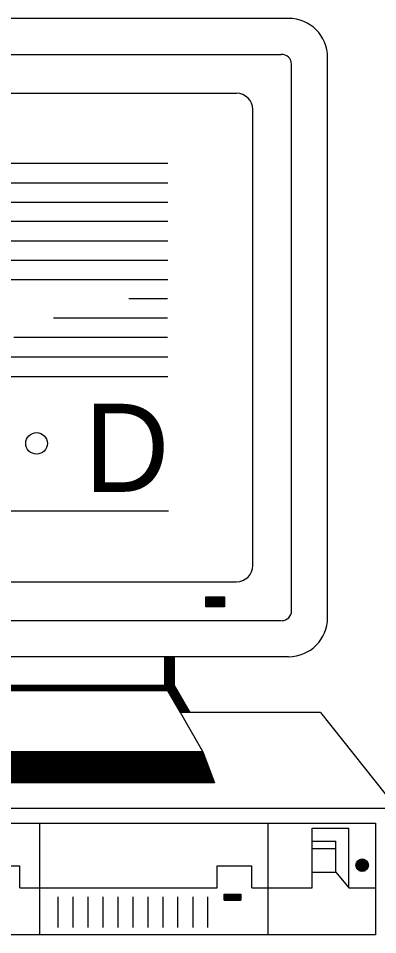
# Model space of a CAD drawing. Extents: x 22369.62 to 22373.29, y 22369.62 to 22372.46.
# Drawn here: x 22372.9001 to 22372.9507, y 22369.7343 to 22369.8633 of the extents above; entities that cross this region are included whole.
import ezdxf

# ---------------------------------------------------------------- set-up
doc = ezdxf.new("R2010")
doc.units = 0
for name, color, linetype in [('Level 2', 7, 'Continuous'), ('Level 25', 7, 'Continuous'), ('Level 3', 7, 'Continuous'), ('Level 5', 7, 'Continuous'), ('Level 7', 7, 'Continuous')]:
    doc.layers.add(name, color=color, linetype=linetype)

msp = doc.modelspace()

# ---------------------------------------------------------------- linework, layer by layer
at = {"layer": 'Level 2'}
for p, q in [((22372.85196, 22369.85273), (22372.93081, 22369.85273)), ((22372.9331, 22369.78628), (22372.9331, 22369.85044)), ((22372.85196, 22369.78399), (22372.93081, 22369.78399)), ((22372.92649, 22369.78183), (22372.9291, 22369.78183)), ((22372.92649, 22369.78176), (22372.9291, 22369.78176)), ((22372.92649, 22369.78168), (22372.9291, 22369.78168)), ((22372.92649, 22369.78158), (22372.9291, 22369.78158)), ((22372.92649, 22369.7815), (22372.9291, 22369.7815)), ((22372.92649, 22369.78143), (22372.9291, 22369.78143)), ((22372.92649, 22369.78134), (22372.9291, 22369.78134)), ((22372.92649, 22369.78126), (22372.9291, 22369.78126)), ((22372.92649, 22369.78118), (22372.9291, 22369.78118)), ((22372.92649, 22369.78109), (22372.9291, 22369.78109)), ((22372.92649, 22369.78101), (22372.9291, 22369.78101)), ((22372.92649, 22369.78093), (22372.9291, 22369.78093)), ((22372.92649, 22369.78085), (22372.9291, 22369.78085)), ((22372.92649, 22369.78076), (22372.9291, 22369.78076)), ((22372.92649, 22369.78068), (22372.9291, 22369.78068)), ((22372.92649, 22369.7806), (22372.9291, 22369.7806)), ((22372.92649, 22369.78052), (22372.9291, 22369.78052)), ((22372.92072, 22369.76941), (22372.92072, 22369.77346)), ((22372.92204, 22369.77343), (22372.92072, 22369.77343)), ((22372.92204, 22369.77334), (22372.92072, 22369.77334)), ((22372.92204, 22369.77327), (22372.92072, 22369.77327)), ((22372.92204, 22369.77318), (22372.92072, 22369.77318)), ((22372.92204, 22369.77309), (22372.92072, 22369.77309)), ((22372.92204, 22369.77301), (22372.92072, 22369.77301)), ((22372.92204, 22369.77294), (22372.92072, 22369.77294)), ((22372.92204, 22369.77285), (22372.92072, 22369.77285)), ((22372.92204, 22369.77276), (22372.92072, 22369.77276)), ((22372.92204, 22369.77268), (22372.92072, 22369.77268)), ((22372.92204, 22369.7726), (22372.92072, 22369.7726)), ((22372.92204, 22369.77252), (22372.92072, 22369.77252)), ((22372.92204, 22369.77244), (22372.92072, 22369.77244)), ((22372.92204, 22369.77235), (22372.92072, 22369.77235)), ((22372.92204, 22369.77227), (22372.92072, 22369.77227)), ((22372.92204, 22369.77219), (22372.92072, 22369.77219)), ((22372.92204, 22369.7721), (22372.92072, 22369.7721)), ((22372.92204, 22369.77203), (22372.92072, 22369.77203)), ((22372.92204, 22369.77194), (22372.92072, 22369.77194)), ((22372.92204, 22369.77185), (22372.92072, 22369.77185)), ((22372.92204, 22369.77178), (22372.92072, 22369.77178)), ((22372.92204, 22369.7717), (22372.92072, 22369.7717)), ((22372.92204, 22369.77161), (22372.92072, 22369.77161)), ((22372.92204, 22369.77152), (22372.92072, 22369.77152)), ((22372.92204, 22369.77145), (22372.92072, 22369.77145)), ((22372.92204, 22369.77136), (22372.92072, 22369.77136)), ((22372.92204, 22369.77128), (22372.92072, 22369.77128)), ((22372.92204, 22369.77121), (22372.92072, 22369.77121)), ((22372.92204, 22369.77111), (22372.92072, 22369.77111)), ((22372.92204, 22369.77103), (22372.92072, 22369.77103)), ((22372.92204, 22369.77095), (22372.92072, 22369.77095)), ((22372.92204, 22369.77087), (22372.92072, 22369.77087)), ((22372.92204, 22369.77079), (22372.92072, 22369.77079)), ((22372.92204, 22369.7707), (22372.92072, 22369.7707)), ((22372.92204, 22369.77061), (22372.92072, 22369.77061)), ((22372.92204, 22369.77054), (22372.92072, 22369.77054)), ((22372.92204, 22369.77046), (22372.92072, 22369.77046)), ((22372.92204, 22369.77037), (22372.92072, 22369.77037)), ((22372.92204, 22369.77029), (22372.92072, 22369.77029)), ((22372.92204, 22369.77021), (22372.92072, 22369.77021)), ((22372.92204, 22369.77012), (22372.92072, 22369.77012)), ((22372.92204, 22369.77004), (22372.92072, 22369.77004)), ((22372.92204, 22369.76997), (22372.92072, 22369.76997)), ((22372.92204, 22369.76987), (22372.92072, 22369.76987)), ((22372.92204, 22369.76979), (22372.92072, 22369.76979)), ((22372.92204, 22369.76972), (22372.92072, 22369.76972)), ((22372.92204, 22369.76963), (22372.92072, 22369.76963)), ((22372.92204, 22369.76955), (22372.92072, 22369.76955)), ((22372.92074, 22369.76939), (22372.89138, 22369.76939)), ((22372.92079, 22369.76931), (22372.89138, 22369.76931)), ((22372.92083, 22369.76923), (22372.89138, 22369.76923)), ((22372.92087, 22369.76914), (22372.89138, 22369.76914)), ((22372.92093, 22369.76906), (22372.89138, 22369.76906)), ((22372.92097, 22369.76898), (22372.89138, 22369.76898)), ((22372.92102, 22369.76889), (22372.89138, 22369.76889)), ((22372.92107, 22369.76882), (22372.89138, 22369.76882)), ((22372.92112, 22369.76873), (22372.89138, 22369.76873)), ((22372.92116, 22369.76864), (22372.89138, 22369.76864)), ((22372.92118, 22369.76863), (22372.89138, 22369.76863)), ((22372.92204, 22369.76946), (22372.92072, 22369.76946)), ((22372.92072, 22369.76941), (22372.92608, 22369.76007)), ((22372.92206, 22369.76938), (22372.92074, 22369.76938)), ((22372.9221, 22369.7693), (22372.92079, 22369.7693)), ((22372.92216, 22369.76922), (22372.92083, 22369.76922)), ((22372.92221, 22369.76914), (22372.92089, 22369.76914)), ((22372.92225, 22369.76905), (22372.92094, 22369.76905)), ((22372.9223, 22369.76897), (22372.92098, 22369.76897)), ((22372.92234, 22369.76888), (22372.92103, 22369.76888)), ((22372.92239, 22369.76881), (22372.92107, 22369.76881)), ((22372.92245, 22369.76873), (22372.92112, 22369.76873)), ((22372.92248, 22369.76863), (22372.92116, 22369.76863)), ((22372.92254, 22369.76855), (22372.92121, 22369.76855)), ((22372.92258, 22369.76848), (22372.92127, 22369.76848)), ((22372.92263, 22369.76839), (22372.92131, 22369.76839)), ((22372.92268, 22369.76831), (22372.92136, 22369.76831)), ((22372.92273, 22369.76823), (22372.9214, 22369.76823)), ((22372.92277, 22369.76814), (22372.92145, 22369.76814)), ((22372.92282, 22369.76806), (22372.9215, 22369.76806)), ((22372.92287, 22369.76798), (22372.92155, 22369.76798)), ((22372.92291, 22369.7679), (22372.92159, 22369.7679)), ((22372.92297, 22369.76781), (22372.92164, 22369.76781)), ((22372.92301, 22369.76773), (22372.9217, 22369.76773)), ((22372.92305, 22369.76765), (22372.92174, 22369.76765)), ((22372.9231, 22369.76757), (22372.92178, 22369.76757)), ((22372.92314, 22369.76749), (22372.92183, 22369.76749)), ((22372.92321, 22369.76739), (22372.92187, 22369.76739)), ((22372.92325, 22369.76732), (22372.92194, 22369.76732)), ((22372.9233, 22369.76724), (22372.92198, 22369.76724)), ((22372.92334, 22369.76715), (22372.92202, 22369.76715)), ((22372.92338, 22369.76708), (22372.92207, 22369.76708)), ((22372.92344, 22369.76699), (22372.92211, 22369.76699)), ((22372.92348, 22369.7669), (22372.92216, 22369.7669)), ((22372.92353, 22369.76682), (22372.92221, 22369.76682)), ((22372.92358, 22369.76675), (22372.92225, 22369.76675)), ((22372.92362, 22369.76666), (22372.92231, 22369.76666)), ((22372.92368, 22369.76657), (22372.92235, 22369.76657)), ((22372.92372, 22369.76649), (22372.9224, 22369.76649)), ((22372.92377, 22369.76641), (22372.92245, 22369.76641)), ((22372.92381, 22369.76633), (22372.9225, 22369.76633)), ((22372.92385, 22369.76625), (22372.92254, 22369.76625)), ((22372.92391, 22369.76616), (22372.92258, 22369.76616)), ((22372.92396, 22369.76608), (22372.92263, 22369.76608)), ((22372.92401, 22369.766), (22372.92269, 22369.766)), ((22372.92405, 22369.76591), (22372.92274, 22369.76591)), ((22372.9241, 22369.76584), (22372.92278, 22369.76584)), ((22372.92414, 22369.76575), (22372.92282, 22369.76575)), ((22372.92419, 22369.76566), (22372.92287, 22369.76566)), ((22372.92608, 22369.76007), (22372.89138, 22369.76007)), ((22372.92609, 22369.76004), (22372.89138, 22369.76004)), ((22372.92612, 22369.75996), (22372.89138, 22369.75996)), ((22372.92616, 22369.75988), (22372.89138, 22369.75988)), ((22372.92619, 22369.75979), (22372.89138, 22369.75979)), ((22372.92622, 22369.75971), (22372.89138, 22369.75971)), ((22372.92625, 22369.75963), (22372.89138, 22369.75963)), ((22372.92628, 22369.75955), (22372.89138, 22369.75955)), ((22372.92631, 22369.75947), (22372.89138, 22369.75947)), ((22372.92633, 22369.75937), (22372.89138, 22369.75937)), ((22372.92636, 22369.7593), (22372.89138, 22369.7593)), ((22372.9264, 22369.75922), (22372.89138, 22369.75922)), ((22372.92644, 22369.75913), (22372.89138, 22369.75913)), ((22372.92646, 22369.75906), (22372.89138, 22369.75906)), ((22372.92649, 22369.75897), (22372.89138, 22369.75897)), ((22372.92653, 22369.75888), (22372.89138, 22369.75888)), ((22372.92655, 22369.7588), (22372.89138, 22369.7588)), ((22372.92658, 22369.75873), (22372.89138, 22369.75873)), ((22372.9266, 22369.75864), (22372.89138, 22369.75864)), ((22372.92664, 22369.75855), (22372.89138, 22369.75855)), ((22372.92668, 22369.75847), (22372.89138, 22369.75847)), ((22372.92671, 22369.75839), (22372.89138, 22369.75839)), ((22372.92674, 22369.75831), (22372.89138, 22369.75831)), ((22372.92677, 22369.75823), (22372.89138, 22369.75823)), ((22372.92679, 22369.75814), (22372.89138, 22369.75814)), ((22372.92682, 22369.75806), (22372.89138, 22369.75806)), ((22372.92686, 22369.75798), (22372.89138, 22369.75798)), ((22372.92688, 22369.75789), (22372.89138, 22369.75789)), ((22372.92691, 22369.75782), (22372.89138, 22369.75782)), ((22372.92695, 22369.75773), (22372.89138, 22369.75773)), ((22372.92699, 22369.75764), (22372.89138, 22369.75764)), ((22372.92701, 22369.75757), (22372.89138, 22369.75757)), ((22372.92704, 22369.75749), (22372.89138, 22369.75749)), ((22372.92706, 22369.7574), (22372.89138, 22369.7574)), ((22372.9271, 22369.75731), (22372.89138, 22369.75731)), ((22372.92713, 22369.75724), (22372.89138, 22369.75724)), ((22372.92715, 22369.75715), (22372.89138, 22369.75715)), ((22372.9272, 22369.75707), (22372.89138, 22369.75707)), ((22372.92723, 22369.757), (22372.89138, 22369.757)), ((22372.92725, 22369.7569), (22372.89138, 22369.7569)), ((22372.92728, 22369.75682), (22372.89138, 22369.75682)), ((22372.92732, 22369.75674), (22372.89138, 22369.75674)), ((22372.92734, 22369.75666), (22372.89138, 22369.75666)), ((22372.92737, 22369.75658), (22372.89138, 22369.75658)), ((22372.9274, 22369.75649), (22372.89138, 22369.75649)), ((22372.92744, 22369.7564), (22372.89138, 22369.7564)), ((22372.92747, 22369.75633), (22372.89138, 22369.75633)), ((22372.9275, 22369.75625), (22372.89138, 22369.75625)), ((22372.92752, 22369.75616), (22372.89138, 22369.75616)), ((22372.92756, 22369.75608), (22372.89138, 22369.75608)), ((22372.92759, 22369.756), (22372.89138, 22369.756)), ((22372.92761, 22369.75591), (22372.89138, 22369.75591)), ((22372.92765, 22369.75583), (22372.89138, 22369.75583)), ((22372.92769, 22369.75576), (22372.89138, 22369.75576)), ((22372.92771, 22369.75569), (22372.89138, 22369.75569)), ((22372.90315, 22369.73434), (22372.90315, 22369.75002)), ((22372.93525, 22369.73434), (22372.93525, 22369.75002)), ((22372.94145, 22369.74094), (22372.94145, 22369.74934)), ((22372.94145, 22369.74934), (22372.94662, 22369.74934)), ((22372.94662, 22369.74094), (22372.94662, 22369.74934)), ((22372.94145, 22369.74752), (22372.94479, 22369.74752)), ((22372.94145, 22369.74647), (22372.94479, 22369.74647)), ((22372.94479, 22369.74315), (22372.94479, 22369.74752)), ((22372.89418, 22369.74403), (22372.90035, 22369.74403)), ((22372.90035, 22369.74094), (22372.90035, 22369.74403)), ((22372.92811, 22369.74403), (22372.93295, 22369.74403)), ((22372.92811, 22369.74094), (22372.92811, 22369.74403)), ((22372.93295, 22369.74094), (22372.93295, 22369.74403)), ((22372.94761, 22369.74412), (22372.94936, 22369.74412)), ((22372.94762, 22369.74422), (22372.94935, 22369.74422)), ((22372.94762, 22369.74405), (22372.94936, 22369.74405)), ((22372.94763, 22369.7443), (22372.94934, 22369.7443)), ((22372.94763, 22369.74397), (22372.94934, 22369.74397)), ((22372.94764, 22369.74388), (22372.94933, 22369.74388)), ((22372.94765, 22369.74437), (22372.94933, 22369.74437)), ((22372.94768, 22369.74446), (22372.94929, 22369.74446)), ((22372.94768, 22369.7438), (22372.94929, 22369.7438)), ((22372.94773, 22369.74454), (22372.94926, 22369.74454)), ((22372.94777, 22369.74463), (22372.94921, 22369.74463)), ((22372.94784, 22369.74471), (22372.94913, 22369.74471)), ((22372.94791, 22369.74479), (22372.94905, 22369.74479)), ((22372.94803, 22369.74487), (22372.94894, 22369.74487)), ((22372.94823, 22369.74495), (22372.94876, 22369.74495)), ((22372.94145, 22369.74315), (22372.94479, 22369.74315)), ((22372.94479, 22369.74315), (22372.94662, 22369.74094)), ((22372.94772, 22369.74372), (22372.94926, 22369.74372)), ((22372.94776, 22369.74363), (22372.94922, 22369.74363)), ((22372.94783, 22369.74355), (22372.94914, 22369.74355)), ((22372.9479, 22369.74348), (22372.94906, 22369.74348)), ((22372.94802, 22369.74339), (22372.94897, 22369.74339)), ((22372.94819, 22369.7433), (22372.94879, 22369.7433)), ((22372.90035, 22369.74094), (22372.92808, 22369.74094)), ((22372.92906, 22369.74002), (22372.93141, 22369.74002)), ((22372.92906, 22369.73995), (22372.93141, 22369.73995)), ((22372.93295, 22369.74094), (22372.94145, 22369.74094)), ((22372.94662, 22369.74094), (22372.95035, 22369.74094)), ((22372.92906, 22369.73985), (22372.93141, 22369.73985)), ((22372.92906, 22369.73977), (22372.93141, 22369.73977)), ((22372.92906, 22369.7397), (22372.93141, 22369.7397)), ((22372.92906, 22369.73961), (22372.93141, 22369.73961)), ((22372.92906, 22369.73953), (22372.93141, 22369.73953)), ((22372.92906, 22369.73944), (22372.93141, 22369.73944)), ((22372.92906, 22369.73936), (22372.93141, 22369.73936)), ((22372.92906, 22369.73928), (22372.93141, 22369.73928)), ((22372.92906, 22369.7392), (22372.93141, 22369.7392))]:
    msp.add_line(p, q, dxfattribs=at)
for points in [[(22372.92649, 22369.78189), (22372.9291, 22369.78189), (22372.9291, 22369.78045), (22372.92649, 22369.78045)], [(22372.92204, 22369.77346), (22372.92204, 22369.76941), (22372.92424, 22369.7656), (22372.92291, 22369.7656), (22372.92072, 22369.76941), (22372.92072, 22369.77346)], [(22372.92072, 22369.76941), (22372.92118, 22369.76863), (22372.89138, 22369.76863), (22372.89138, 22369.76941)], [(22372.92608, 22369.76007), (22372.92771, 22369.75569), (22372.89138, 22369.75569), (22372.89138, 22369.76007)], [(22372.8326, 22369.75002), (22372.95035, 22369.75002), (22372.95035, 22369.73434), (22372.8326, 22369.73434)], [(22372.92906, 22369.74002), (22372.93141, 22369.74002), (22372.93141, 22369.7392), (22372.92906, 22369.7392)]]:
    msp.add_lwpolyline(points, close=True, dxfattribs=at)
for centre, radius in [((22372.90269, 22369.80346), 0.00152), ((22372.94849, 22369.74412), 0.000875)]:
    msp.add_circle(centre, radius, dxfattribs=at)
for centre, start, end in [((22372.93081, 22369.85043), 0, 90), ((22372.93081, 22369.78628), 270, 0)]:
    msp.add_arc(centre, 0.00229, start, end, dxfattribs=at)
at = {"layer": 'Level 25'}
msp.add_line((22372.92072, 22369.76941), (22372.89138, 22369.76941), dxfattribs=at)
at = {"layer": 'Level 3'}
for p, q in [((22372.84463, 22369.86326), (22372.93813, 22369.86326)), ((22372.84558, 22369.85819), (22372.93709, 22369.85819)), ((22372.94363, 22369.77896), (22372.94363, 22369.85776)), ((22372.93856, 22369.77991), (22372.93856, 22369.85681)), ((22372.84558, 22369.77854), (22372.93709, 22369.77854)), ((22372.84463, 22369.77346), (22372.93813, 22369.77346))]:
    msp.add_line(p, q, dxfattribs=at)
for centre, radius, start, end in [((22372.93813, 22369.85775), 0.0055, 0, 90), ((22372.93718, 22369.8568), 0.00137, 0, 93.8704), ((22372.93718, 22369.7799), 0.00138, 270, 0), ((22372.93813, 22369.77895), 0.0055, 270, 0)]:
    msp.add_arc(centre, radius, start, end, dxfattribs=at)
at = {"layer": 'Level 5'}
for p, q in [((22372.86218, 22369.84286), (22372.92113, 22369.84286)), ((22372.89709, 22369.84013), (22372.92113, 22369.84013)), ((22372.89709, 22369.83741), (22372.92113, 22369.83741)), ((22372.89709, 22369.8347), (22372.92113, 22369.8347)), ((22372.89709, 22369.83197), (22372.92113, 22369.83197)), ((22372.89709, 22369.82924), (22372.92113, 22369.82924)), ((22372.86218, 22369.82651), (22372.92113, 22369.82651)), ((22372.92112, 22369.8238), (22372.91568, 22369.8238)), ((22372.92112, 22369.82107), (22372.90506, 22369.82107)), ((22372.92112, 22369.81835), (22372.89948, 22369.81835)), ((22372.86218, 22369.81562), (22372.92113, 22369.81562)), ((22372.86218, 22369.81289), (22372.92113, 22369.81289)), ((22372.86218, 22369.79399), (22372.92124, 22369.79399)), ((22372.92204, 22369.76941), (22372.92204, 22369.77346)), ((22372.92204, 22369.76941), (22372.92424, 22369.7656)), ((22372.94264, 22369.7656), (22372.92291, 22369.7656)), ((22372.94264, 22369.7656), (22372.95335, 22369.75209)), ((22372.95335, 22369.75209), (22372.89138, 22369.75209))]:
    msp.add_line(p, q, dxfattribs=at)
at = {"layer": 'Level 7'}
for p, q in [((22372.90574, 22369.73534), (22372.90574, 22369.73965)), ((22372.90784, 22369.73534), (22372.90784, 22369.73965)), ((22372.90995, 22369.73534), (22372.90995, 22369.73965)), ((22372.91205, 22369.73534), (22372.91205, 22369.73965)), ((22372.91416, 22369.73534), (22372.91416, 22369.73965)), ((22372.91627, 22369.73534), (22372.91627, 22369.73965)), ((22372.91838, 22369.73534), (22372.91838, 22369.73965)), ((22372.92049, 22369.73534), (22372.92049, 22369.73965)), ((22372.92258, 22369.73534), (22372.92258, 22369.73965)), ((22372.9247, 22369.73534), (22372.9247, 22369.73965)), ((22372.9268, 22369.73534), (22372.9268, 22369.73965))]:
    msp.add_line(p, q, dxfattribs=at)

# ---------------------------------------------------------------- texts
at = {"layer": 'Level 5'}
msp.add_text('D', height=0.0124, dxfattribs=at).set_placement((22372.90939, 22369.79664))

doc.saveas('drawing.dxf')
